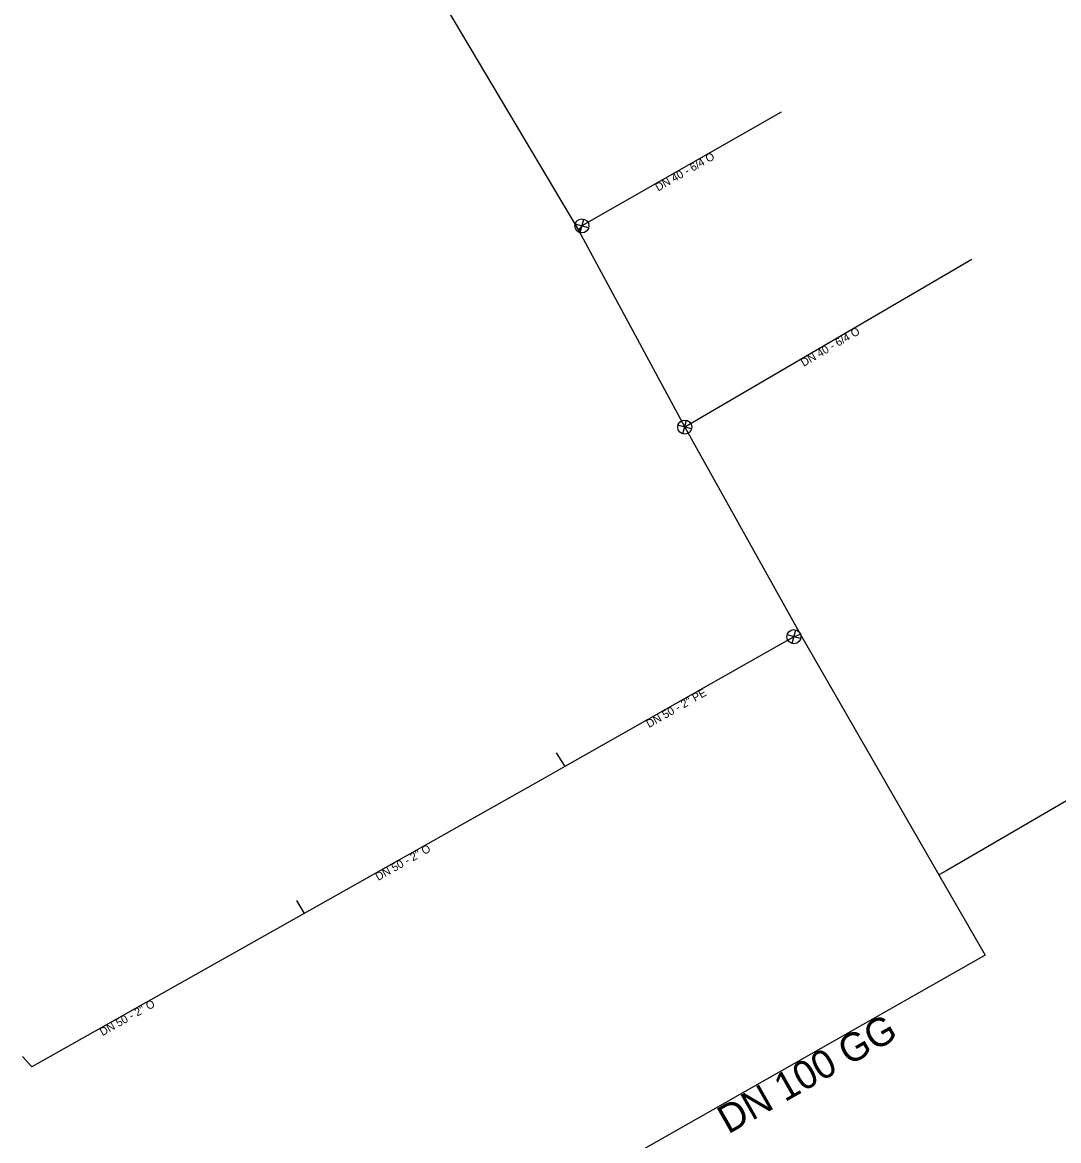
# Model space of a CAD drawing. Extents: x -443562 to -443270, y -1122830 to -1122511.
# Drawn here: x -443398.8 to -443339.8, y -1122738.8 to -1122675.2 of the extents above; entities that cross this region are included whole.
import ezdxf

# ---------------------------------------------------------------- set-up
doc = ezdxf.new("R2010")
doc.units = 0
for name, color, linetype in [('_pripojka_priblizne_', 7, 'Continuous'), ('_voda_smvak_prevzato_z_dokumentace_', 7, 'Continuous'), ('Default', 7, 'Continuous'), ('MoLevel 32', 7, 'Continuous'), ('MoLevel 46', 7, 'Continuous'), ('MoLevel 53', 7, 'Continuous')]:
    doc.layers.add(name, color=color, linetype=linetype)

# ---------------------------------------------------------------- blocks, each defined once
blk = doc.blocks.new('_uzaver_pripojka_')
at = {"layer": 'Default'}
for p, q in [((-0.000035, -0.000035), (0.000035, 0.000035)), ((0.000035, -0.000035), (-0.000035, 0.000035))]:
    blk.add_line(p, q, dxfattribs=at)
for radius in [0.00005, 0.0000025]:
    blk.add_circle((0, 0), radius, dxfattribs=at)

msp = doc.modelspace()

# ---------------------------------------------------------------- linework, layer by layer
at = {"layer": '_pripojka_priblizne_'}
for p, q in [((-443368.399, -1122716.758), (-443367.903, -1122717.539)), ((-443383.174, -1122725.145), (-443382.724, -1122725.887))]:
    msp.add_line(p, q, dxfattribs=at)
for points in [[(-443355.61, -1122680.32), (-443366.94, -1122686.79), (-443367.13, -1122687.04)], [(-443344.76, -1122688.7), (-443361.09, -1122698.23), (-443361.09, -1122698.23)], [(-443354.51, -1122710.032), (-443354.88, -1122710.15), (-443367.903, -1122717.539)], [(-443367.903, -1122717.539), (-443368.966, -1122718.142), (-443382.725, -1122725.887)], [(-443382.725, -1122725.887), (-443398.212, -1122734.606), (-443398.758, -1122734.03)]]:
    msp.add_lwpolyline(points, dxfattribs=at)
at = {"layer": '_voda_smvak_prevzato_z_dokumentace_'}
for points in [[(-443384.03, -1122658.96), (-443377.77, -1122669.15), (-443367.13, -1122687.04), (-443361.09, -1122698.23), (-443354.51, -1122710.032), (-443346.631, -1122723.693)], [(-443323.09, -1122710), (-443346.19, -1122723.44), (-443346.631, -1122723.693)], [(-443346.631, -1122723.693), (-443343.999, -1122728.257), (-443367.303, -1122741.497)]]:
    msp.add_lwpolyline(points, dxfattribs=at)

# ---------------------------------------------------------------- block references
at = {"layer": 'MoLevel 53'}
for p, xscale, yscale, rotation in [((-443366.94, -1122686.79), 7999.999999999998, 8000, 29.72854064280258), ((-443361.09, -1122698.23), 7999.999999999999, 8000.000000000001, 30.2673435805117), ((-443354.88, -1122710.15), 7999.999999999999, 7999.999999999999, 29.293383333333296)]:
    msp.add_blockref('_uzaver_pripojka_', p, dxfattribs=dict(at, xscale=xscale, yscale=yscale, rotation=rotation))

# ---------------------------------------------------------------- texts
at = {"layer": 'MoLevel 32'}
for s, rotation, p in [('DN 40 - 6/4 O', 29.72854, (-443362.604, -1122684.838)), ('DN 40 - 6/4 O', 30.26735, (-443354.325, -1122694.809)), ("DN 50 - 2'' PE", 29.56898, (-443363.121, -1122715.349)), ("DN 50 - 2'' O", 29.37729, (-443378.523, -1122724.044)), ("DN 50 - 2'' O", 29.37729, (-443394.2, -1122732.87))]:
    msp.add_text(s, height=0.455, rotation=rotation, dxfattribs=at).set_placement(p)
at = {"layer": 'MoLevel 46'}
msp.add_text('DN 100 GG', height=1.6049, rotation=29.60268, dxfattribs=at).set_placement((-443358.617, -1122738.46))

doc.saveas('drawing.dxf')
